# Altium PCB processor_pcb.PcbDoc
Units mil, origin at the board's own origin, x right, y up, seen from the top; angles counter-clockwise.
Board outline 4100 x 3155 mil, 2 copper layers (Top Layer, Bottom Layer); 81 components, 68 nets, 372 pads, 55 vias.
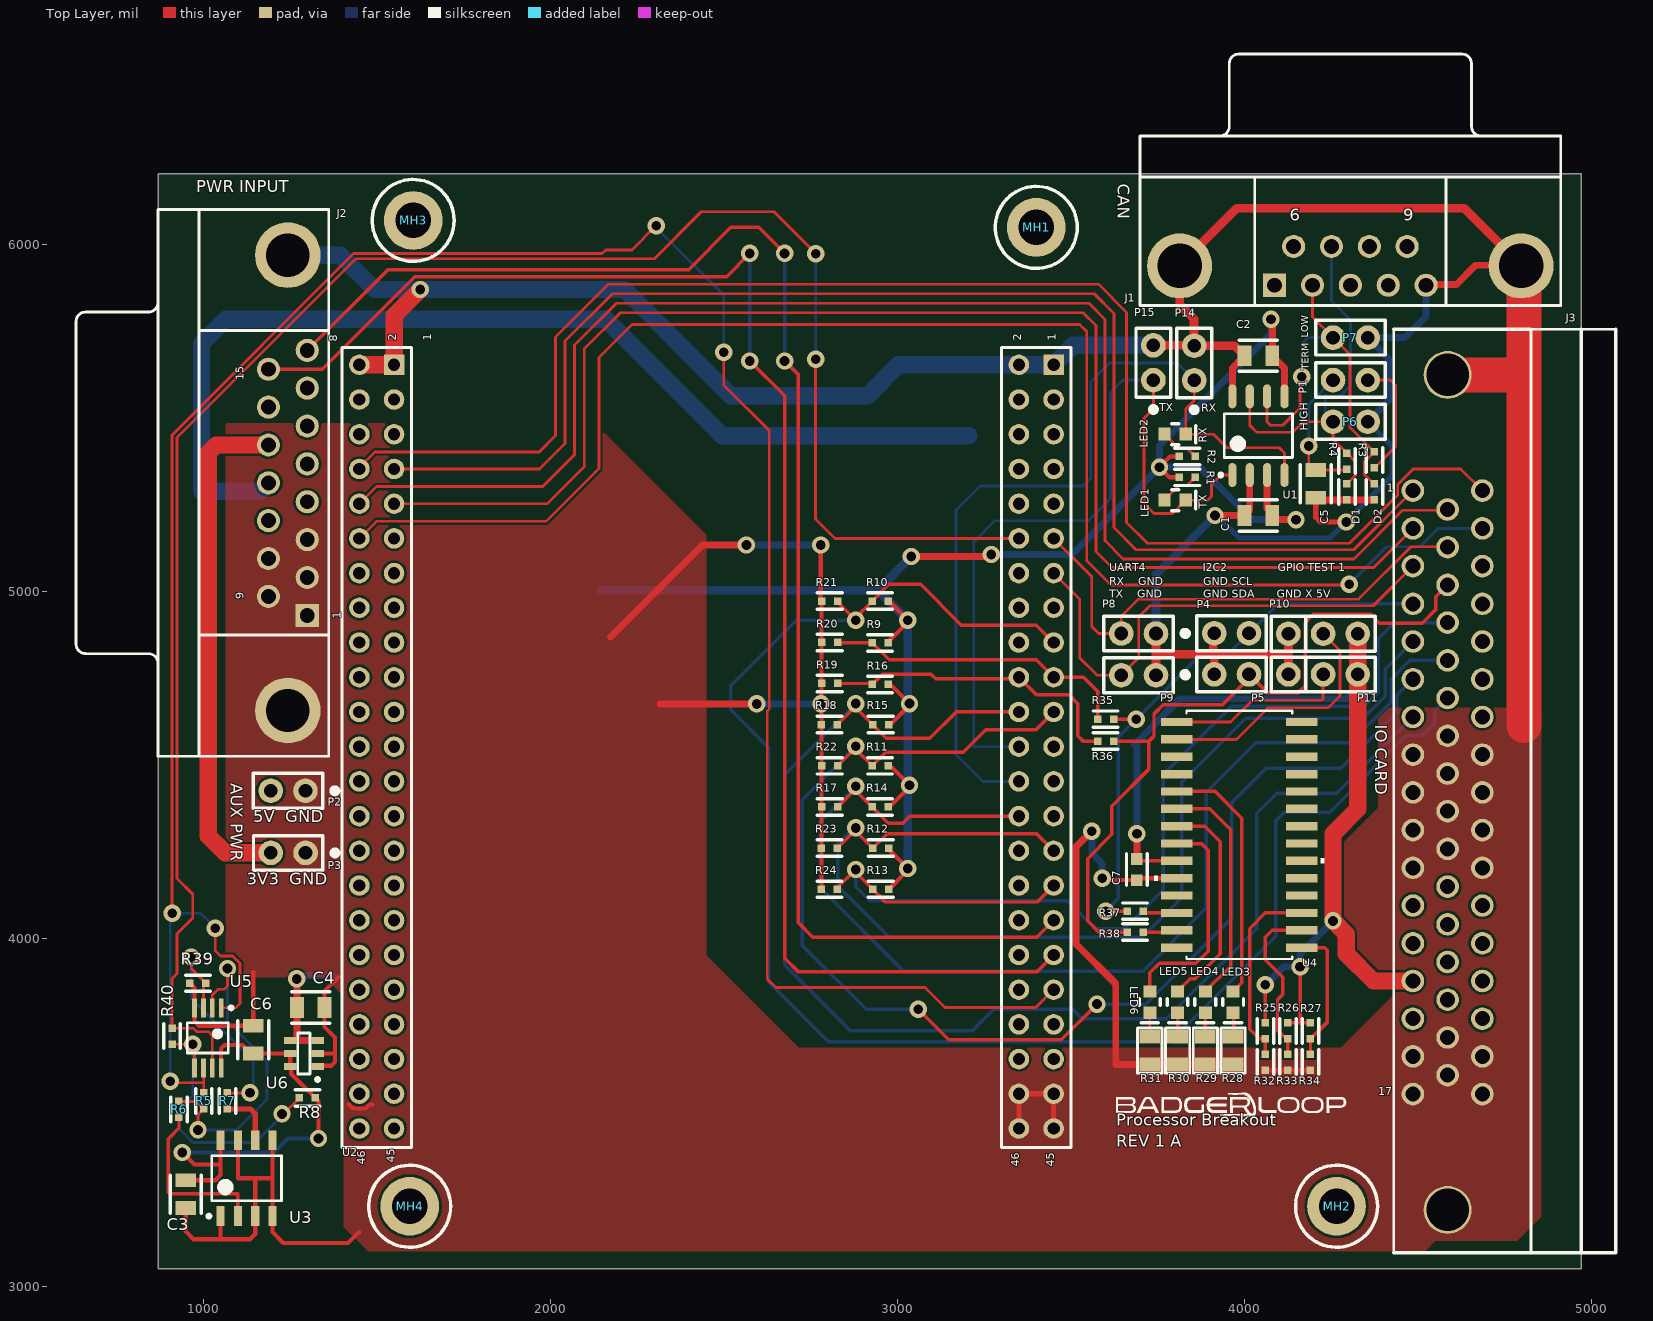
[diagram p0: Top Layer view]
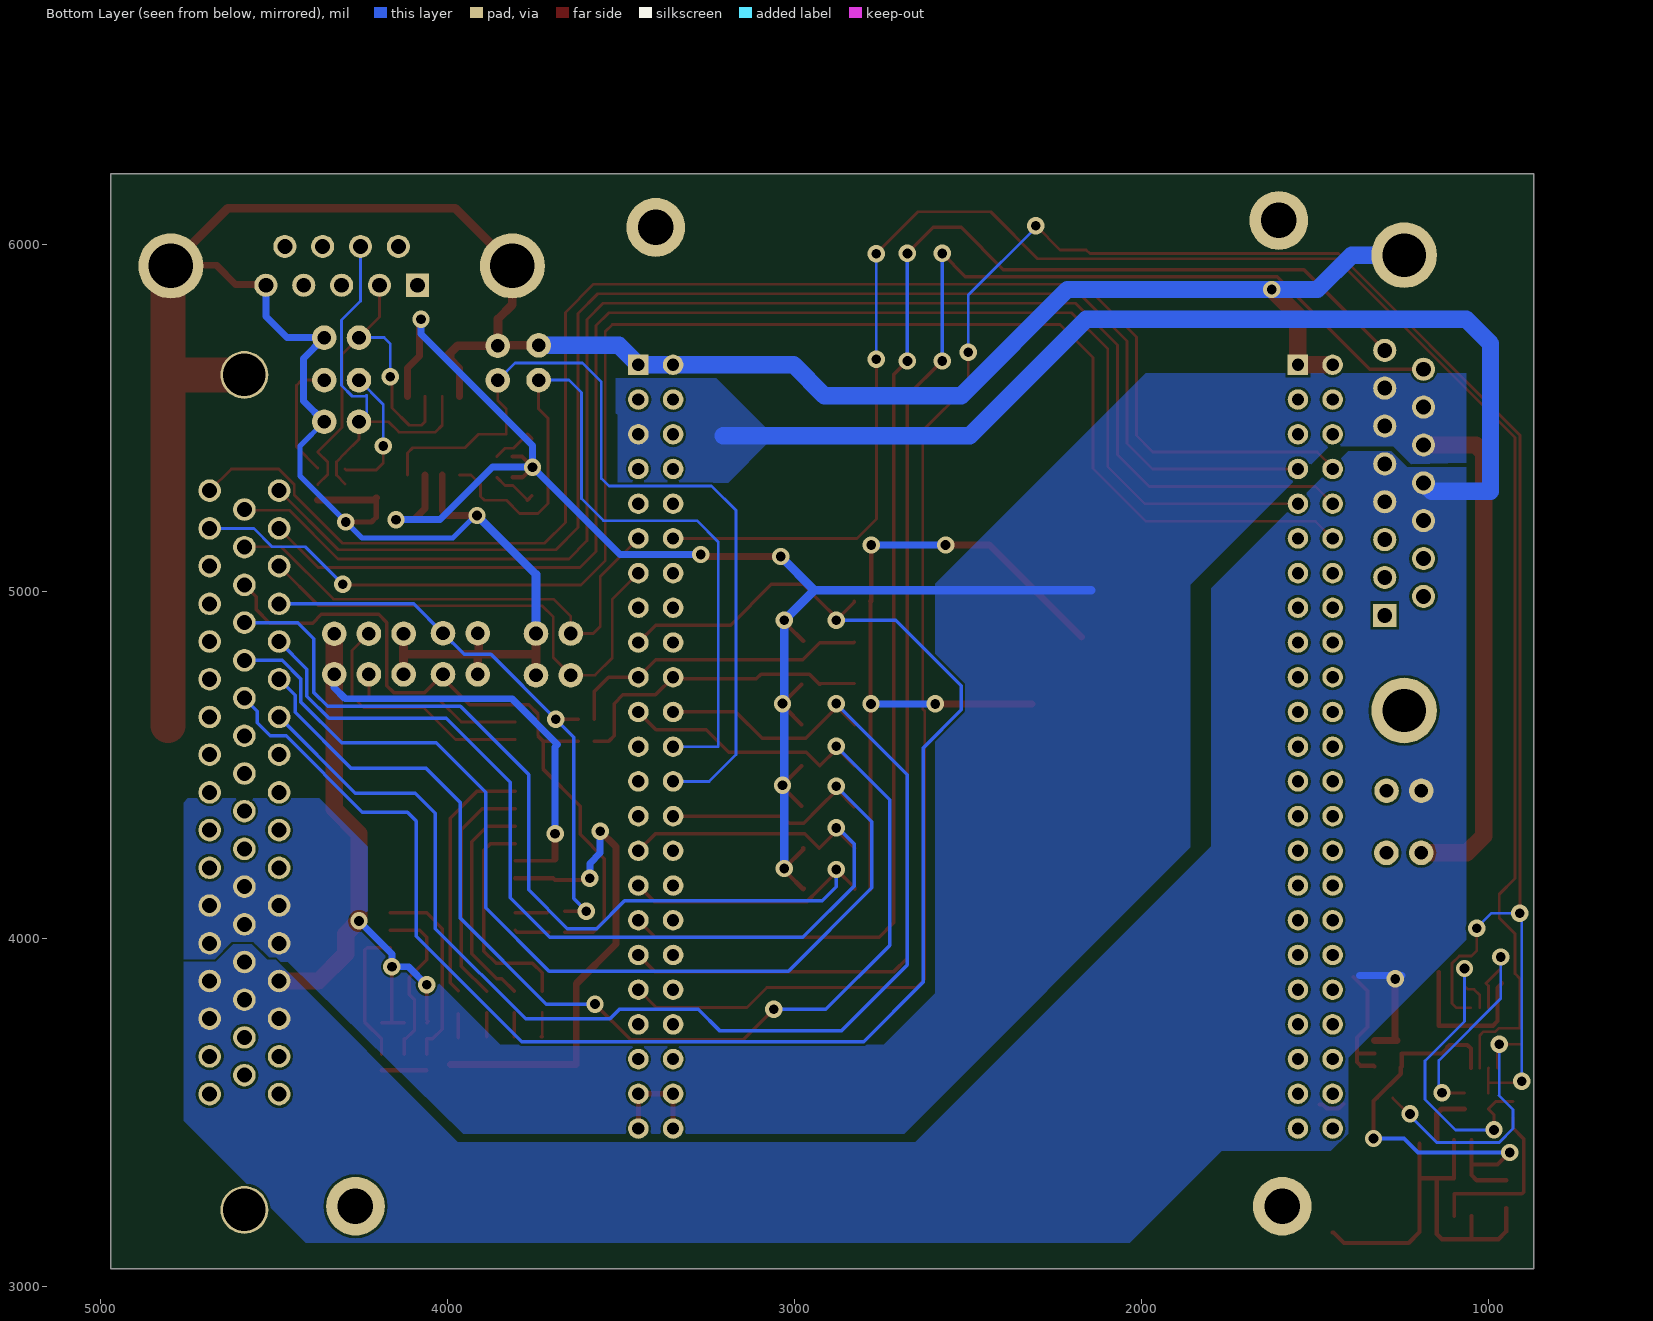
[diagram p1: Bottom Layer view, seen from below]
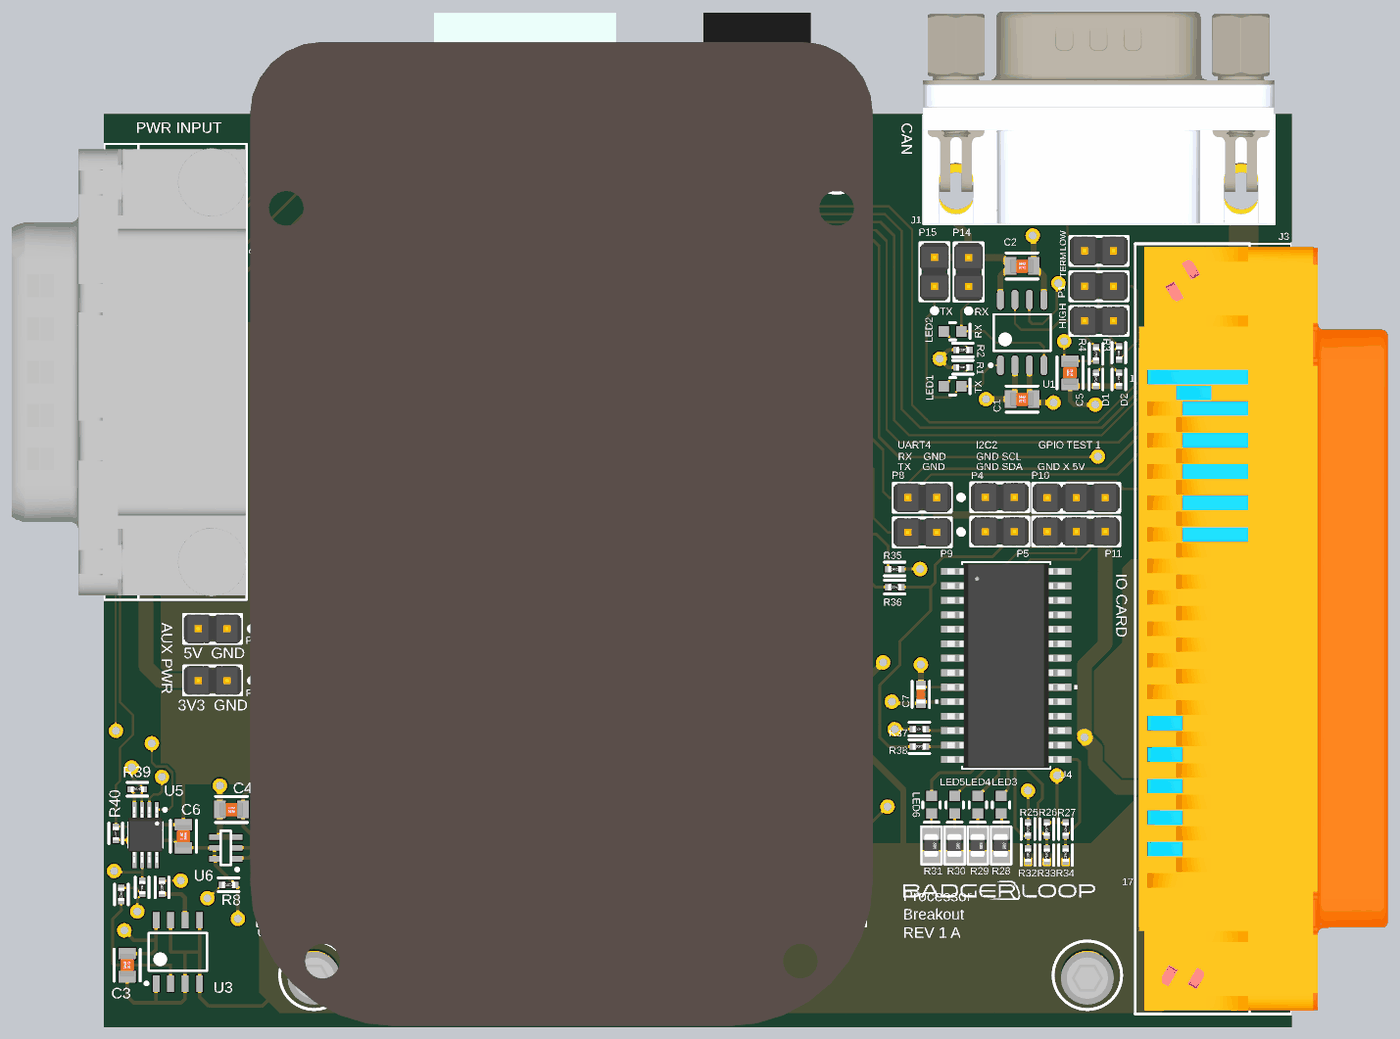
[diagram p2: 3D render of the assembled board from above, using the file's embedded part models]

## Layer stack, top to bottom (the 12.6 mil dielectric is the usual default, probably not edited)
Top Solder: solder mask 0.4, Solder Resist, Dk 3.5
Top Layer: signal copper 1.4
Dielectric 1: dielectric 12.6, FR-4, Dk 4.8
Bottom Layer: signal copper 1.4
Bottom Solder: solder mask 0.4, Solder Resist, Dk 3.5

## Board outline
870,3050 4970,3050 4970,6205 870,6205

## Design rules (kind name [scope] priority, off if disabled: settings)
AcuteAngle [All] p1: minimum=6.00000000000000E+0001 checktracksonly=FALSE
BoardOutlineClearance "Board Outline Silk Exception" [(OnLayer('Bottom Overlay') OR OnLayer('top overlay'))] p1: gap=0 ignorepadtopadclearanceinfootprint=FALSE
BoardOutlineClearance [All] p2: gap=10 ignorepadtopadclearanceinfootprint=FALSE except(0: Arc-SplitContinuation Track-SplitContinuation SMDPad-SplitContinuation THPad-SplitContinuation Via-SplitContinuation Fill-SplitContinuation Poly-SplitContinuation Region-SplitContinuation Text-SplitContinuation)
Clearance [All] p1: gap=7 ignorepadtopadclearanceinfootprint=TRUE except(0: Arc-Hole Track-Hole SMDPad-Hole THPad-Hole Via-Hole Fill-Hole Poly-Hole Region-Hole Text-Hole)
DiffPairsRouting [All] p1: maxlimit=10 minlimit=10 mostfreqgap=10 toplayer_minwidth=15 toplayer_maxwidth=15 toplayer_prefwidth=15 bottomlayer_minwidth=15 bottomlayer_maxwidth=15 bottomlayer_prefwidth=15 maxuncoupledlength=500
HoleSize [All] p1: absolutevalues=TRUE maxlimit=200 minlimit=1 maxpercent=80.000 minpercent=20.000
MinimumSolderMaskSliver [All] p1: minsoldermaskwidth=8
PlaneClearance [All] p1: clearance=50
PlaneConnect [All] p1: planeconnectstyle=Direct reliefexpansion=20 reliefentries=4 reliefconductorwidth=20 reliefairgap=10
PolygonConnect [All] p1: connectstyle=Direct reliefconductorwidth=10 reliefentries=4 polygonreliefangle="90 Angle" airgapwidth=10
RoutingVias [All] p1: holewidth=10 width=30 viastyle="Through Hole" minholewidth=10 minwidth=30 maxholewidth=10 maxwidth=30
SilkToSilkClearance [All] p1: silktosilkclearance=3
SilkToSolderMaskClearance [IsPad] p1: minsilkscreentomaskgap=2 clearancetoexposedcopper=TRUE
SolderMaskExpansion [All] p1: expansion=4
UnRoutedNet [All] p1: checkbadconnections=TRUE
Width [All] p1: maxlimit=100 minlimit=7 preferedwidth=7 minimp=50.000000 maximp=50.000000 favimp=50.000000
22 further rules are at their usual default settings.

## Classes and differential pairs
component class processor_breakout_conn: C7 J2 J3 LED3 LED4 LED5 LED6 P10 P11 R25 R26 R27 R28 R29 R30 R31 R32 R33 R34 R37 R38 U4
component class processor_beaglebone: MH1 MH2 MH3 MH4 P4 P5 P8 P9 R9 R10 R11 R12 R13 R14 R15 R16 R17 R18 R19 R20 R21 R22 R23 R24 R35 R36 U2
component class processor_main_connector: C1 C2 C3 C4 C5 C6 D1 D2 J1 LED1 LED2 P1 P2 P3 P6 P7 P14 P15 R1 R2 R3 R4 R5 R6 R7 R8 R39 R40 U1 U3 U5 U6
differential pair PRESS1: +PRESS1_P -PRESS1_N

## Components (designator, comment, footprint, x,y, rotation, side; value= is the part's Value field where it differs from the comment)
C1 "0.10µF" SMD-0805C 4040,5220 r270 top
C2 "0.10µF" SMD-0805C 4040,5680 r270 top
C3 "0.10µF" SMD-0805C 950,3265 r0 top
C4 "1µF" SMD-0805C 1310,3802.72 r90 top
C5 "4700pF" SMD-0805C 4205,5311.07 r0 top
C6 "1µF" SMD-0805C 1144.07,3710.03 r180 top
C7 "0.10µF" SMD-0603C 3690,4200 r0 top
D1 "ESD Diode" SMD-0402-RES 4295,5288.07 r180 top
D2 "ESD Diode" SMD-0402-RES 4373.88,5288.07 r180 top
J1 "D Connector 9" DSUB1.385-2H9 4305,6313.11 r0 top
J2 "D Connector 15" DSUB1.385-2H15 870,5314.06 r90 top locked
J3 "Connector 50" 050DSUB1.27-H96 4485,5291.53 r270 top
LED1 "LED ORANGE 0603" "LED 0603 ORANGE" 3799.99,5264.17 r0 top
LED2 "LED ORANGE 0603" "LED 0603 ORANGE" 3799.99,5454.17 r0 top
LED3 "RED" "LED 0603 RED" 3967,3818.37 r270 top
LED4 "RED" "LED 0603 RED" 3887,3818.37 r270 top
LED5 "GREEN" "LED 0603 GREEN" 3807,3818.37 r270 top
LED6 "GREEN" "LED 0603 GREEN" 3727,3818.37 r270 top
MH1 "4-40 Mount Hole" MH 3400,6050 r0 top
MH2 "4-40 Mount Hole" MH 4265,3230 r0 top
MH3 "4-40 Mount Hole" MH 1605,6070 r0 top
MH4 "4-40 Mount Hole" MH 1595,3230 r0 top
P1 "Header 2" "Pin Header 1x2 TH Pitch 2.54mm" 4355,5610 r180 top
P2 "Header 2" "Pin Header 1x2 TH Pitch 2.54mm" 1294.66,4426.88 r180 top
P3 "Header 2" "Pin Header 1x2 TH Pitch 2.54mm" 1295,4247.93 r180 top
P4 "Header 2" "Pin Header 1x2 TH Pitch 2.54mm" 3912.76,4880.78 r0 top
P5 "Header 2" "Pin Header 1x2 TH Pitch 2.54mm" 3912.76,4762.18 r0 top
P6 "Header 2" "Pin Header 1x2 TH Pitch 2.54mm" 4255,5490 r0 top
P7 "Header 2" "Pin Header 1x2 TH Pitch 2.54mm" 4255,5732.36 r0 top
P8 "Header 2" "Pin Header 1x2 TH Pitch 2.54mm" 3745,4880 r180 top
P9 "Header 2" "Pin Header 1x2 TH Pitch 2.54mm" 3745,4760 r180 top
P10 "Header 3" "Pin Header 1x3 TH Pitch 2.54mm" 4126.42,4879.26 r0 top
P11 "Header 3" "Pin Header 1x3 TH Pitch 2.54mm" 4126.42,4762.24 r0 top
P14 "Header 2" "Pin Header 1x2 TH Pitch 2.54mm" 3855,5609.17 r90 top
P15 "Header 2" "Pin Header 1x2 TH Pitch 2.54mm" 3737.36,5610 r90 top
R1 "120" SMD-0402-RES 3835,5330 r90 top
R2 "120" SMD-0402-RES 3835,5390 r90 top
R3 "60.4" SMD-0402-RES 4373.88,5380 r180 top
R4 "60.4" SMD-0402-RES 4295.08,5376.54 r0 top
R5 "34k" SMD-0402-RES 1001.7,3533.33 r180 top
R6 "34k" SMD-0402-RES 930,3509 r180 top
R7 "34k" SMD-0402-RES 1070,3533.33 r180 top
R8 "34k" SMD-0402-RES 1300.04,3542.36 r270 top
R9 "10k" SMD-0402-RES 2950,4853.15 r90 top
R10 "10k" SMD-0402-RES 2950,4973.15 r90 top
R11 "10k" SMD-0402-RES 2950,4498.86 r90 top
R12 "10k" SMD-0402-RES 2952,4261.72 r90 top
R13 "10k" SMD-0402-RES 2952,4143.15 r90 top
R14 "10k" SMD-0402-RES 2950,4380.29 r90 top
R15 "10k" SMD-0402-RES 2952,4617.44 r90 top
R16 "10k" SMD-0402-RES 2950,4733.15 r90 top
R17 "10k" SMD-0402-RES 2805,4380.29 r90 top
R18 "10k" SMD-0402-RES 2804,4617.44 r90 top
R19 "10k" SMD-0402-RES 2805,4736.01 r90 top
R20 "10k" SMD-0402-RES 2805,4854.58 r90 top
R21 "10k" SMD-0402-RES 2805,4973.15 r90 top
R22 "10k" SMD-0402-RES 2805,4498.86 r90 top
R23 "10k" SMD-0402-RES 2804,4261.72 r90 top
R24 "10k" SMD-0402-RES 2804,4143.15 r90 top
R25 "0.0" SMD-0402-RES 4060,3735 r180 top
R26 "0.0" SMD-0402-RES 4125,3735 r180 top
R27 "0.0" SMD-0402-RES 4190,3735 r180 top
R28 "220" SMD-0805-RES 3967,3678.37 r180 top
R29 "220" SMD-0805-RES 3887,3678.37 r180 top
R30 "220" SMD-0805-RES 3807,3678.37 r180 top
R31 "220" SMD-0805-RES 3727,3678.37 r180 top
R32 "0.0" SMD-0402-RES 4060,3645 r180 top
R33 "0.0" SMD-0402-RES 4125,3645 r180 top
R34 "0.0" SMD-0402-RES 4190,3645 r180 top
R35 "0.0" SMD-0402-RES 3600,4633.15 r270 top
R36 "0.0" SMD-0402-RES 3600,4570.25 r90 top
R37 "0.0" SMD-0402-RES 3685,4080 r90 top
R38 "0.0" SMD-0402-RES 3685,4020 r90 top
R39 "34k" SMD-0402-RES 985,3872.4 r90 top
R40 "34k" SMD-0402-RES 910.32,3720 r180 top
U1 "SN65HVD256" SOIC127P630X175-8N 4040,5450 r90 top
U2 "BEAGLEBONE Black Rev C Headers" BEAGLEBONE_TOPSIDE 1550,5653.98 r0 top
U3 "NPP-301A-100AT" SOIC127P610X280-8N 1125,3310.75 r90 top
U4 "MCP23017T-E/SO" SOIC28-W_MC-M 3985,4300 r0 top value=Value
U5 "LTC6081ISMS8#PBF" TSOP65P490X110-8N 1013.43,3715 r270 top
U6 "ADR3433" SOT95P280X145-6N 1290.32,3670 r180 top

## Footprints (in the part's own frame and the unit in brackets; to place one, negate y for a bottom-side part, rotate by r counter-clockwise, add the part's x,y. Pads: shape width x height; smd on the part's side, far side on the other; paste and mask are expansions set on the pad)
050DSUB1.27-H96 [mil] "Connector; D Subminiature; 96 Position; Right Angle; Pitch 1.27 mm"
  round 65 hole 43.31: 1(0,0) 2(108.66,0) 3(217.32,0) 4(325.98,0) 5(434.65,0) 6(543.31,0) 7(651.97,0) 8(760.63,0) 9(869.29,0) 10(977.95,0) 11(1086.61,0) 12(1195.28,0) 13(1303.94,0) 14(1412.6,0) 15(1521.26,0) 16(1629.92,0) 17(1738.58,0) 18(54.33,100) 19(162.97,100) 20(271.6,100) 21(380.24,100) 22(488.87,100) 23(597.51,100) 24(706.14,100) 25(814.78,100) 26(923.41,100) 27(1032.05,100) 28(1140.68,100) 29(1249.32,100) 30(1357.95,100) 31(1466.59,100) 32(1575.22,100) 33(1683.86,100) 34(0,200) 35(108.66,200) 36(217.32,200) 37(325.98,200) 38(434.65,200) 39(543.31,200) 40(651.97,200) 41(760.63,200) 42(869.29,200) 43(977.95,200) 44(1086.61,200) 45(1195.28,200) 46(1303.94,200) 47(1412.6,200) 48(1521.26,200) 49(1629.92,200) 50(1738.58,200)
  round 138 hole 122.05: 51(-333.46,100) 52(2072.05,100)
  silkscreen extent -465,-55 2195,585, body extent -454,-42 2184,817, height 547
BEAGLEBONE_TOPSIDE [mm] "Connector; Header; 24x2 Position"
  rect 1.5x1.5 hole 0.9: 1(48.26,0) 101(0,0)
  round 1.5 hole 0.9: 2(45.72,0) 3(48.26,-2.54) 4(45.72,-2.54) 5(48.26,-5.08) 6(45.72,-5.08) 7(48.26,-7.62) 8(45.72,-7.62) 9(48.26,-10.16) 10(45.72,-10.16) 11(48.26,-12.7) 12(45.72,-12.7) 13(48.26,-15.24) 14(45.72,-15.24) 15(48.26,-17.78) 16(45.72,-17.78) 17(48.26,-20.32) 18(45.72,-20.32) 19(48.26,-22.86) 20(45.72,-22.86) 21(48.26,-25.4) 22(45.72,-25.4) 23(48.26,-27.94) 24(45.72,-27.94) 25(48.26,-30.48) 26(45.72,-30.48) 27(48.26,-33.02) 28(45.72,-33.02) 29(48.26,-35.56) 30(45.72,-35.56) 31(48.26,-38.1) 32(45.72,-38.1) 33(48.26,-40.64) 34(45.72,-40.64) 35(48.26,-43.18) 36(45.72,-43.18) 37(48.26,-45.72) 38(45.72,-45.72) 39(48.26,-48.26) 40(45.72,-48.26) 41(48.26,-50.8) 42(45.72,-50.8) 43(48.26,-53.34) 44(45.72,-53.34) 45(48.26,-55.88) 46(45.72,-55.88) 102(-2.54,0) 103(0,-2.54) 104(-2.54,-2.54) 105(0,-5.08) 106(-2.54,-5.08) 107(0,-7.62) 108(-2.54,-7.62) 109(0,-10.16) 110(-2.54,-10.16) 111(0,-12.7) 112(-2.54,-12.7) 113(0,-15.24) 114(-2.54,-15.24) 115(0,-17.78) 116(-2.54,-17.78) 117(0,-20.32) 118(-2.54,-20.32) 119(0,-22.86) 120(-2.54,-22.86) 121(0,-25.4) 122(-2.54,-25.4) 123(0,-27.94) 124(-2.54,-27.94) 125(0,-30.48) 126(-2.54,-30.48) 127(0,-33.02) 128(-2.54,-33.02) 129(0,-35.56) 130(-2.54,-35.56) 131(0,-38.1) 132(-2.54,-38.1) 133(0,-40.64) 134(-2.54,-40.64) 135(0,-43.18) 136(-2.54,-43.18) 137(0,-45.72) 138(-2.54,-45.72) 139(0,-48.26) 140(-2.54,-48.26) 141(0,-50.8) 142(-2.54,-50.8) 143(0,-53.34) 144(-2.54,-53.34) 145(0,-55.88) 146(-2.54,-55.88)
  silkscreen extent -3.81,-57.28 49.53,1.27, body extent -4.46,-66.04 50.15,22.86, height 12.6
DSUB1.385-2H9 [mm] "Connector; D Subminiature; 9 Position; Right Angle; Pitch 1.385 mm"
  rect 1.69x1.69 hole 1.09: 1(-5.54,-10.92)
  round 1.69 hole 1.09: 2(-2.77,-10.92) 3(0,-10.92) 4(2.77,-10.92) 5(5.54,-10.92) 6(-4.155,-8.08) 7(-1.385,-8.08) 8(1.385,-8.08) 9(4.155,-8.08)
  round 4.76 hole 3.26: 10(-12.495,-9.5) 11(12.495,-9.5)
  silkscreen extent -15.4,-12.4 15.4,6, body extent -15.43,-12.37 15.37,6.22, height 12.55
DSUB1.385-2H15 [mm] "Connector; D Subminiature; 15 Position; Right Angle; Pitch 1.385 mm"
  rect 1.69x1.69 hole 1.09: 1(-9.695,-10.92)
  round 1.69 hole 1.09: 2(-6.925,-10.92) 3(-4.155,-10.92) 4(-1.385,-10.92) 5(1.385,-10.92) 6(4.155,-10.92) 7(6.925,-10.92) 8(9.695,-10.92) 9(-8.31,-8.08) 10(-5.54,-8.08) 11(-2.77,-8.08) 12(0,-8.08) 13(2.77,-8.08) 14(5.54,-8.08) 15(8.31,-8.08)
  round 4.8 hole 3.18: 16(-16.66,-9.5) 17(16.66,-9.5)
  silkscreen extent -20,-12.5 20,6, body extent -19.68,-12.47 19.64,8.13, height 13.45
"LED 0603 GREEN" [mm] "Chip Diode, 2-Leads, Body 1.60x0.80mm, IPC Medium Density"
  rect 0.9x0.95 smd: 1(-0.775,0) 2(0.775,0)
  silkscreen extent -0.25,-0.76 1.52,0.76, body extent -0.8,-0.4 0.8,0.4, height 0.8
"LED 0603 ORANGE" [mm] "Chip Diode, 2-Leads, Body 1.60x0.80mm"
  rect 0.9x0.95 smd: 1(-0.775,0) 2(0.775,0)
  silkscreen extent -0.25,-0.76 1.52,0.76, body extent -0.8,-0.4 0.8,0.4, height 0.8
"LED 0603 RED" [mm] "Chip Diode, 2-Leads, Body 1.60x0.80mm, IPC Medium Density"
  rect 0.9x0.95 smd: 1(-0.775,0) 2(0.775,0)
  silkscreen extent -0.25,-0.76 1.52,0.76, body extent -0.8,-0.4 0.8,0.4, height 0.8
MH [mm] "#10 Mount Hole"
  round 4.3 hole 2.6 unplated: 2(0,0)
  silkscreen extent -3,-3 3,3, body extent -2.32,-2.58 2.32,2.07, height 2.84
"Pin Header 1x2 TH Pitch 2.54mm" [mm] "PinHeader 1x2 TH Pitch 2.54mm"
  round 1.8 hole 1: 1(0,0) 2(2.54,0)
  silkscreen extent -1.27,-1.27 3.81,1.27, body extent -1.27,-1.27 3.81,1.27, height 9.5
"Pin Header 1x3 TH Pitch 2.54mm" [mm] "PinHeader 1x3 TH Pitch 2.54mm"
  round 1.8 hole 1: 1(0,0) 2(2.54,0) 3(5.08,0)
  silkscreen extent -1.27,-1.27 6.35,1.27, body extent -1.27,-1.27 6.35,1.27, height 9.5
SMD-0402-RES [mm]
  rect 0.55x0.55 smd: 1(0,0.584) 2(0,-0.584)
  silkscreen extent -0.6,-0.9 0.6,0.9, body extent -0.28,-0.57 0.27,0.58, height 0.41
SMD-0603C [mm]
  rect 0.85x0.85 smd: 1(0,0.775) 2(0,-0.775)
  silkscreen extent -0.76,-1.14 0.76,1.14, body extent -0.4,-0.8 0.4,0.8, height 0.9
SMD-0805-RES [mil]
  rect 60x40 smd: 1(0,40) 2(0,-40)
  silkscreen extent -35,-65 35,65, body extent -24,-39 26,39, height 31
SMD-0805C [mil]
  rect 60x40 smd: 1(0,40) 2(0,-40)
  silkscreen extent -45,-55 45,55, body extent -25,-39 25,39, height 35
SOIC28-W_MC-M [mil]
  rect 90x24 smd paste+0 mask+0: 1(-180,325) 2(-180,275) 3(-180,225) 4(-180,175) 5(-180,125) 6(-180,75) 7(-180,25) 8(-180,-25) 9(-180,-75) 10(-180,-125) 11(-180,-175) 12(-180,-225) 13(-180,-275) 14(-180,-325) 15(180,-325) 16(180,-275) 17(180,-225) 18(180,-175) 19(180,-125) 20(180,-75) 21(180,-25) 22(180,25) 23(180,75) 24(180,125) 25(180,175) 26(180,225) 27(180,275) 28(180,325)
  silkscreen extent -245,-358 245,358, body extent -203,-353 203,353, height 104
SOIC127P610X280-8N [mm] "SOIC, 8-Leads, Body 5.10x4.10mm, Pitch 1.27mm, IPC Medium Density"
  rect 1.45x0.6 smd: 1(-2.775,1.905) 2(-2.775,0.635) 3(-2.775,-0.635) 4(-2.775,-1.905) 5(2.775,-1.905) 6(2.775,-0.635) 7(2.775,0.635) 8(2.775,1.905)
  silkscreen extent -2.9,-2.55 1.65,2.88, body extent -2.05,-2.55 2.05,2.55, height 2.8
SOIC127P630X175-8N [mm] "SOIC, 8-Leads, Body 4.90x3.90mm, Pitch 1.27mm, IPC Medium Density"
  oval 1.75x0.6 smd: 1(-2.875,1.905) 2(-2.875,0.635) 3(-2.875,-0.635) 4(-2.875,-1.905) 5(2.875,-1.905) 6(2.875,-0.635) 7(2.875,0.635) 8(2.875,1.905)
  silkscreen extent -3,-2.5 1.6,2.88, body extent -2,-2.5 2,2.5, height 1.75
SOT95P280X145-6N [mm] "SOT23, 6-Leads, Body 2.90x2.80mm, Pitch 0.95mm, IPC Medium Density"
  rect 0.9x0.5 smd: 1(-1,0.95) 2(-1,0) 3(-1,-0.95) 4(1,-0.95) 5(1,0) 6(1,0.95)
  silkscreen extent -1.13,-1.5 0.45,2.02, body extent -0.85,-1.5 0.85,1.5, height 1.45
TSOP65P490X110-8N [mm] "TSOP, 8-Leads, Body 3.00x3.00mm, Pitch 0.65mm, IPC Medium Density"
  rect 1.4x0.35 smd: 1(-2.2,0.975) 2(-2.2,0.325) 3(-2.2,-0.325) 4(-2.2,-0.975) 5(2.2,-0.975) 6(2.2,-0.325) 7(2.2,0.325) 8(2.2,0.975)
  silkscreen extent -2.32,-1.5 1.1,1.83, body extent -2.45,-1.5 2.45,1.5, height 1.1

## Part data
C1 C2 C3: library part GCD21BR71H104KA01L, "CAP CER 0.1UF 50V X7R 0805", Digi-Key Part Number=490-11955-1-ND, Manufacturer="Murata Electronics North America", Operating Temperature="-55°C ~ 125°C", Package / Case="0805 (2012 Metric)", Ratings=AEC-Q200, Temperature Coefficient=X7R, Tolerance=±10%, Voltage=50V
C4: library part GCJ21BR71H105KA01L, "CAP CER 1UF 50V X7R 0805", Digi-Key Part Number=490-10667-1-ND, Manufacturer="Murata Electronics North America", Operating Temperature="-55°C ~ 125°C", Package / Case="0805 (2012 Metric)", Ratings=AEC-Q200, Temperature Coefficient=X7R, Tolerance=±10%, Voltage=50V
C5: library part GCM2165C1H472JA16D, "CAP CER 4700PF 50V NP0 0805", Digi-Key Part Number=490-4973-1-ND, Manufacturer="Murata Electronics North America", Operating Temperature="-55°C ~ 125°C", Package / Case="0805 (2012 Metric)", Ratings=AEC-Q200, Temperature Coefficient="C0G, NP0", Tolerance=±5%, Voltage=50V
C6: library part GRT21BC81E105ME13L, "CAP CER 1UF 25V X6S 0805", Digi-Key Part Number=490-12352-1-ND, Manufacturer="Murata Electronics North America", Operating Temperature="-55°C ~ 105°C", Package / Case="0805 (2012 Metric)", Ratings=AEC-Q200, Temperature Coefficient=X6S, Tolerance=±20%, Voltage=25V
C7: library part GCJ188R72A104KA01D, "CAP CER 0.1UF 100V X7R 0603", Digi-Key Part Number=490-13420-1-ND, Manufacturer="Murata Electronics North America", Operating Temperature="-55°C ~ 125°C", Package / Case="0603 (1608 Metric)", Ratings=AEC-Q200, Temperature Coefficient=X7R, Tolerance=±10%, Voltage=100V
D1 D2: "ESD Supressor", Manufacturer=EZAEG, Manufacturer P/N=Panasonic
J1: "Receptacle Assembly, 9 Position, Right Angle", PackageDocument=O
J2: "Receptacle Assembly, 15 Position, Right Angle", PackageDocument=O
J3: "Receptacle Header Assemby", PackageDocument=B
LED1 LED2: "A-0603UOC", Color=ORANGE, Manufacturer="Lighthouse LEDs", Package / Case=0603
LED3 LED4: library part "LED RED 0603", "Red 631nm LED Indication - Discrete 2V 0603 (1608 Metric)", Manufacturer="Lite-On Inc.", Manufacturer P/N=LTST-C190KRKT, Package / Case=0603
LED5 LED6: library part "LED GREEN 0603", Manufacturer="Lite-On Inc.", Manufacturer P/N=LTST-C190KGKT, Package / Case=0603
P1 P2 P3 P4 P5 P6 P7 P8 P9 P14 P15: "Header, 2-Pin"
P10 P11: "Header, 3-Pin"
R1 R2: library part ERJ-2GEJ121X, "RES SMD 120 OHM 5% 1/10W 0402", Digi-Key Part Number=P120JCT-ND, Manufacturer="Panasonic Electronic Components", Operating Temperature="-55°C ~ 155°C", Package / Case="0402 (1005 Metric)", Power (Watts)="0.1W, 1/10W", Supplier Device Package=0402, Temperature Coefficient=±200ppm/°C, Tolerance=±5%
R3 R4: library part ERJ-2RKF60R4X, "RES SMD 60.4 OHM 1% 1/10W 0402", Digi-Key Part Number=P60.4LCT-ND, Manufacturer="Panasonic Electronic Components", Operating Temperature="-55°C ~ 155°C", Package / Case="0402 (1005 Metric)", Power (Watts)="0.1W, 1/10W", Supplier Device Package=0402, Temperature Coefficient=±100ppm/°C, Tolerance=±1%
R5 R6 R7 R8 R39 R40: library part ERJ-2RKF3402X, "RES SMD 34K OHM 1% 1/10W 0402", Digi-Key Part Number=P34.0KLCT-ND, Manufacturer="Panasonic Electronic Components", Operating Temperature="-55°C ~ 155°C", Package / Case="0402 (1005 Metric)", Power (Watts)="0.1W, 1/10W", Supplier Device Package=0402, Temperature Coefficient=±100ppm/°C, Tolerance=±1%
R9 R10 R11 R12 R13 R14 R15 R16 R17 R18 R19 R20 R21 R22 R23 R24: library part ERJ-2GEJ103X, "RES SMD 10K OHM 5% 1/10W 0402", Digi-Key Part Number=P10KJCT-ND, Manufacturer="Panasonic Electronic Components", Operating Temperature="-55°C ~ 155°C", Package / Case="0402 (1005 Metric)", Power (Watts)="0.1W, 1/10W", Supplier Device Package=0402, Temperature Coefficient=±200ppm/°C, Tolerance=±5%
R25 R26 R27 R32 R33 R34 R35 R36 R37 R38: library part ERJ-2GE0R00X, "RES SMD 0.0OHM JUMPER 1/10W 0402", Digi-Key Part Number=P0.0JCT-ND, Manufacturer="Panasonic Electronic Components", Operating Temperature="-55°C ~ 155°C", Package / Case="0402 (1005 Metric)", Power (Watts)="0.1W, 1/10W", Supplier Device Package=0402, Temperature Coefficient=-, Tolerance=Jumper
R28 R29 R30 R31: library part ERJ-6ENF2200V, "RES SMD 220 OHM 1% 1/8W 0805", Digi-Key Part Number=P220CCT-ND, Manufacturer="Panasonic Electronic Components", Operating Temperature="-55°C ~ 155°C", Package / Case="0805 (2012 Metric)", Power (Watts)="0.125W, 1/8W", Supplier Device Package=0805, Temperature Coefficient=±100ppm/°C, Tolerance=±1%
U1: "IC TXRX CAN 5V HS 8SOIC", Manufacturer=TI, Manufacturer P/N=SN65HVD256DR
U2: library part Beaglebone, "Beaglebone Black Rev C Header"
U3: "SENSOR PRES 15PSIA SO8 SMD", Manufacturer="Amphenol Advanced Sensors"
U4: "Imported"
U5: "IC OPAMP GP 3.5MHZ RRO 8MSOP", Manufacturer="Linear Technology", Manufacturer P/N=LTC6081IMS8#PBF
U6: "IC VREF SERIES 3.3V SOT23-6", Manufacturer="Analog Devices", Manufacturer P/N=ADR3433ARJZ-R7

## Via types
v1: diameter 50, hole 28, Top Layer to Bottom Layer, 55 vias

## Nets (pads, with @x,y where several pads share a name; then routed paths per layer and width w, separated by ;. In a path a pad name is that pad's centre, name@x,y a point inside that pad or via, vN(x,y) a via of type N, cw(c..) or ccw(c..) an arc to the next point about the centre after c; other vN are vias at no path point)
3V3_PRESS_IN: C3.1 C6.1 R8.1 U3.8 U5.8 U6.5 U6.6 | length 1290.2
  Top Layer w12: v1(940,3385) 975,3350 1050,3350 ; C3.1 1035,3305 1050,3320 1050,3350 ; U3.8 1050,3350 ; U5.8 1051.81,3684.57 1062.24,3695 1113.04,3695 1120.07,3687.97 1120.07,3684.03 1134.07,3670.03 C6.1 U6.5 ; U6.5 U6.6 1253.61,3629.93 1253.61,3611.79 R8.1 1332.07,3533.33 v1(1332.07,3425)
  Bottom Layer w12: v1(940,3385) 1203.91,3385 1243.91,3425 v1(1332.07,3425)
AIN0: U2.39
CAN1_H: D1.2 J1.7 P6.1 R4.1 U1.7 | length 1157.1
  Top Layer w8: U1.7 4015,5480 4035,5460 4140,5460 4170,5490 P6.1 4255,5439.61 R4.1 4320,5374.61 4320,5336.07 D1.2
  Bottom Layer w8: J1.7@4250.47,5996.81 4250.47,5837.39 4305,5782.87 4305,5594.33 4274.23,5563.57 4235.77,5563.57 4232.77,5566.56 4232.77,5512.23 P6.1
CAN1_L: D2.2 J1.2 P7.1 R3.2 U1.6 | length 1150.4
  Top Layer w8: U1.6 4065,5490 4075,5480 4110,5480 4160,5530 4160,5615 v1(4165,5620) ; J1.2@4195.94,5885 4195.94,5791.42 P7.1 4303.6,5683.76 4303.6,5473.28 R3.2 4345,5374.12 4345,5338.43 D2.2@4373.88,5309.55
  Bottom Layer w8: v1(4165,5620) 4165,5715 4182.36,5732.36 P7.1
CAN1_RX: LED2.2 P14.1 U1.4 U2.26 | length 2497.7
  Top Layer w8: P14.1 3855,5551.36 3830.5,5526.86 LED2.2 3910.83,5454.17 3950,5415 4100,5415 4115,5400 U1.4
  Bottom Layer w8: U2.26 3246.02,4453.98 3168.98,4531.02 3168.98,5235 3238.98,5305 3535,5305 3556.65,5326.65 3556.65,5605 3610.83,5659.17 3805,5659.17 P14.1
CAN1_TX: LED1.2 P15.1 U1.1 U2.24 | length 2309.4
  Top Layer w8: P15.1 3737.36,5527.36 3710,5500 3710,5255 3739.21,5225.79 3792.12,5225.79 LED1.2 3894.17,5264.17 3905,5275 3905,5310 3931.81,5336.81 U1.1
  Bottom Layer w8: U2.24 3220,4553.98 3220,5143.98 3281.02,5205 3550.68,5205 3614.17,5268.49 3614.17,5574.17 3650,5610 P15.1
CURR_SENSE: J2.15 U2.35 | length 4408.4
  Top Layer w10: J2.15 1342.84,5641.22 1609.67,5908.05 1968.05,5908.05 2508.05,5908.05 v1(2575,5975) ; v1(2575,5665) 2675,5565 2675,3945 2715,3905 3401.02,3905 U2.35
  Bottom Layer w10: v1(2575,5665) v1(2575,5975)
GND: C1.2 C2.2 C3.2 C4.2 C5.2 C6.2 C7.2 D1.1 D2.1 J1.5 J1.10 J1.11 J2.1 J2.2 J2.3 J2.9 J2.10 J2.16 J2.17 J3.8 J3.9 J3.10 J3.11 J3.16 J3.17 J3.24 J3.25 J3.26 J3.27 J3.32 J3.33 J3.41 J3.42 J3.43 J3.44 J3.49 J3.50 J3.51 J3.52 P2.1 P3.1 P4.1 P5.1 P6.2 P7.2 P8.1 P9.1 P10.1 P11.1 P14.2 P15.2 R17.1 R18.1 R19.1 R20.1 R21.1 R22.1 R23.1 R24.1 R28.1 R29.1 R30.1 R31.1 R32.1 R33.1 R34.1 R39.1 U1.2 U1.8 U2.1 U2.2 U2.43 U2.44 U2.45 U2.46 U2.101 U2.102 U3.1 U3.3 U3.4 U3.5 U3.7 U4.10 U5.4 U6.1 U6.2 | length 15976.4
  Top Layer w12: C3.2 950,3157 972,3135 1050,3135 ; R39.1 975.04,3859.36 U5.4 975.04,3763.27 988.28,3750.03 C6.2 1144.07,3904.92 1144,3905 ; U3.1 1050,3135 ; U3.7 1100,3310.75 1150,3310.75 ; U3.5@1200,3410 1200,3310.75 ; U6.1 1332.09,3635 1369.87,3635 1380,3645.13 1380,3670 ; U6.2 1380,3670 ; 1390,3890.82 1390,3890.33 1350,3850.33 C4.2 1350,3746.17 1380,3716.17 1380,3670 ; 1419.22,3524.62 1432.38,3511.45 1467.62,3511.45 1479.72,3523.55 1487.59,3523.55 ; 1450,3154.62 1447.71,3154.62 1417.66,3124.56 1230.83,3124.56 1200,3155.39 U3.4 1200,3310.75 ; R21.1@2779,4973.15 2781,4971.15 2781,4677.18 R18.1 R23.1 R24.1 ; v1(2779,5135) 2779,5062.26 ; 2780,5061.26 2779,5062.26 ; R21.1 2779,4976.15 2779,5062.26 ; v1(3590,4175) 3590,4173.2 3586.29,4169.49 C7.2 3695.51,4175 U4.10 ; R32.1 R33.1 R34.1 ; 1050,3135 1135,3135 1150,3150 U3.3 1150,3310.75 ; 1150,3310.75 1200,3310.75
  Top Layer w15: U2.46 U2.44 U2.43 U2.45 ; C5.2 4205,5215 4218.93,5201.07 v1(4292.61,5201.07)
  Top Layer w20: 2174.01,4870.26 2438.76,5135 v1(2565,5135) ; 2315.86,4677.18 v1(2595,4677.18) ; v1(3560,4310.72) 3515,4265.72 3515,3985 3629.07,3870.93 3629.07,3638.37 R31.1 R30.1 R29.1 R28.1 R28.1@3992,3638.37 ; v1(3915,5220) C1.2 4015,5235 U1.2 ; U1.8 3965,5645 3990,5670 C2.2@3990,5680 ; C5.2 4211,5265.07 D1.1 D2.1 ; J1.5@4523.11,5885 4610,5885 4665.91,5940.91 J1.11@4796.93,5940.91
  Top Layer w25: P15.2 P14.2@3854.17,5710 ; P9.1 3745,4820 ; P8.1 3745,4820 ; P5.1 3912.76,4817.24 3910,4820 ; P4.1 3910,4878.02 3910,4820 ; C2.2 3970.83,5709.17 P14.2 P14.2@3854.17,5710 ; P11.1 4126.42,4820 ; P10.1 4126.42,4820 ; J1.11@4796.93,5940.91 4632.83,6105 3977.17,6105 3813.07,5940.91 J1.10 3813.07,5826.93 3854.17,5785.83 P14.2@3854.17,5710 ; 3745,4820 3910,4820 ; 3910,4820 4126.42,4820
  Top Layer w50: U2.102 U2.101 1550,5796.05 v1(1625,5871.05)
  Top Layer w100: J3.51 4795,5625 4805,5615 ; J1.11@4796.93,5940.91 4805,5932.83 4805,5615 ; 4805,4615 4805,5615
  Bottom Layer w15: v1(3915,5220) 3920,5220 3985,5155 4246.54,5155 v1(4292.61,5201.07) 4425,5333.46 4425,5420 P6.2
  Bottom Layer w20: v1(2565,5135) v1(2779,5135) ; v1(2595,4677.18) v1(2780,4677.18) ; v1(3560,4310.72) 3560,4247.15 3590,4217.15 v1(3590,4175) ; P6.2 4415,5550 4415,5672.36 P7.2 4462.42,5732.36 4523.11,5793.06 J1.5 J1.5@4523.11,5885
  Bottom Layer w25: P8.1 3745,5050 v1(3915,5220)
  Bottom Layer w50: J2.17 1395.04,5969.96 1493.95,5871.05 v1(1625,5871.05) 2213.95,5871.05 2520,5565 2913.97,5565 3002.95,5653.98 U2.2 U2.1 3506.02,5710 P15.2
GPIO_44: J3.35 U2.112 | length 4442.5
  Top Layer w8: U2.112 1499.17,5203.15 1988.15,5203.15 2140,5355 2140,5675 2235,5770 3525,5770 3545.68,5749.32 3545.68,5089.32 3615.2,5019.8 4299.43,5019.8 v1(4301.52,5021.89)
  Bottom Layer w8: v1(4301.52,5021.89) 4409.63,5130 4505,5130 4557.87,5182.87 J3.35
GPIO_49: U2.23
GPIO_66: J3.1 U2.107 | length 4054.2
  Top Layer w8: U2.107 1968.98,5353.98 2042.57,5427.57 2042.57,5722.29 2179.12,5858.84 3566.94,5858.84 3623.92,5801.86 3623.92,5184.99 3687.71,5121.2 4314.67,5121.2 J3.1
GPIO_67: J3.34 U2.108 | length 4414.5
  Top Layer w8: U2.108@1450.66,5359.34 1494.47,5403.15 1968.15,5403.15 2015.1,5450.1 2015.1,5733.67 2167.74,5886.32 3522.16,5886.32 3578.83,5886.32 3660,5805.15 3660,5200 3720,5140 4302.13,5140 4441.5,5279.37 4441.5,5309.55 4485.92,5353.98 4622.56,5353.98 J3.34
GPIO_68: J3.18 U2.110 | length 4295.7
  Top Layer w8: U2.110 1499.17,5303.15 1978.15,5303.15 2070.05,5395.05 2070.05,5710.91 2190.5,5831.36 3551.42,5831.37 3597.84,5784.95 3597.84,5147.4 3650.24,5095 4315,5095 4455,5235 J3.18@4585,5235
GPIO_69: J3.2 U2.109 | length 4093.8
  Top Layer w8: U2.109 1991.42,5253.98 2097.52,5360.08 2097.52,5699.53 2201.88,5803.89 3535.09,5803.89 3571.76,5767.22 3571.76,5116.1 3617.86,5070 4372.13,5070 J3.2
GPIO_115: U2.27
GPIO_117: U2.25
GPIO_A_0: U4.21
GPIO_A_1: U4.22
GPIO_A_2: U4.23
GPIO_A_3: U4.24
GPIO_A_4: U4.25
GPIO_A_5: U4.26
GPIO_A_6: U4.27
GPIO_A_7: U4.28
I2C2_SCL: J3.4 P4.2 R35.1 R37.1 | length 1646.6
  Top Layer w10: v1(3600,4080) R37.1 ; R35.1 v1(3687.71,4633.15)
  Bottom Layer w10: v1(3600,4080) 3636.67,4116.67 3636.67,4581.67 3677.71,4622.71 v1@3687.71,4622.71 ; v1(3687.71,4633.15) 3874.56,4820 3951.98,4820 P4.2 4097.53,4965.55 J3.4
I2C2_SCL_BB: R9.1 R20.2 R35.2 U2.19 | length 887.5
  Top Layer w10: R20.2 2829.43,4853.15 R9.1 2975.95,4804.2 3399.78,4804.2 U2.19 3536.02,4753.98 3577,4713 R35.2
I2C2_SDA: J3.20 P5.2 R36.2 R38.1 | length 2102.3
  Top Layer w10: R36.2 3724.71,4570.25 ; R38.1 3580,4020 3548,4052 3548,4231.58 3617.86,4301.45 3617.86,4382.86 3724.71,4489.71 3724.71,4570.25 ; J3.20 4550.93,4985.86 4550.93,4949.07 4511.85,4910 4388.15,4910 4363.15,4935 4198.3,4935 4175,4911.7 4175,4730 4155,4710 4065,4710 P5.2 P5.2 4012.76,4751.38 3936.38,4675 3766.16,4675 3739.21,4648.05 3739.21,4584.75 3724.71,4570.25
I2C2_SDA_BB: R16.1 R19.2 R36.1 U2.20 | length 900.6
  Top Layer w10: R19.2 2924.14,4736.01 R16.1 2957,4763.15 3096.61,4763.15 3110,4749.76 3345.79,4749.76 U2.20 3400.83,4703.15 3495,4703.15 3520,4678.15 3520,4585 3534.75,4570.25 R36.1
I2C_RESET: U4.18
INTA_1: U4.20
INTB_1: U4.19
LED_GPB4: LED3.1 U4.5 | length 725.5
  Top Layer w10: U4.5 3915,4425 3992,4348 3992,3873.89 LED3.1@3969,3850.89
LED_GPB5: LED4.1 U4.6 | length 676.2
  Top Layer w10: U4.6 3900,4375 3960,4315 3960,3921.89 LED4.1
LED_GPB6: LED5.1 U4.7 | length 634.3
  Top Layer w10: U4.7 3885,4325 3930,4280 3930,3957.24 3857.76,3885 3843.11,3885 LED5.1
LED_GPB7: LED6.1 U4.8 | length 636.2
  Top Layer w10: LED6.1 3727,3902.38 3727.38,3902.38 3755,3930 3860,3930 3895,3965 3895,4255.83 3875.83,4275 U4.8
NetC5_1: C5.1 P1.2 R4.2 | length 387.3
  Top Layer w8: v1(4185,5420) 4185,5371.07 C5.1 4292.61,5351.07 R4.2
  Bottom Layer w8: v1(4185,5420) 4185,5540 P1.2
NetLED1_1: LED1.1 R1.2 | length 133.4
  Top Layer w8: LED1.1 3811.69,5306.38 3834.38,5306.38 R1.2
  Top Layer w10: LED1.1@3756.99,5276.66 LED1.1
NetLED2_1: LED2.1 R2.2 | length 132.8
  Top Layer w8: LED2.1 3810.03,5413.62 3834.38,5413.62 R2.2
  Top Layer w10: LED2.1@3756.99,5441.68 LED2.1
NetLED3_2: LED3.2 R28.2 | length 69.5
  Top Layer w10: R28.2@3969,3715.37 LED3.2@3969,3784.86
NetLED4_2: LED4.2 R29.2 | length 69.5
  Top Layer w10: R29.2 LED4.2
NetLED5_2: LED5.2 R30.2 | length 69.5
  Top Layer w10: R30.2 LED5.2
NetLED6_2: LED6.2 R31.2 | length 72.5
  Top Layer w8: R31.2 LED6.2
  Top Layer w10: R31.2 R31.2@3730,3718.37
NetP1_1: P1.1 R3.1 | length 349.5
  Top Layer w8: P1.1 4420,5610 4435,5595 4435,5418.12 R3.1
NetR5_1: R5.1 R6.2 U5.2 | length 949.4
  Top Layer w8: R6.2 980.03,3532 R5.1 985,3493.63 v1(985,3450) ; U5.2 1026.22,3838.82 1042.4,3855 1060,3855 1070,3865 v1(1070,3915)
  Bottom Layer w8: v1(985,3450) 1096,3450 1183.92,3537.92 1183.92,3648.89 1070,3762.81 v1(1070,3915)
NetR7_2: R7.2 R39.2 U5.3 | length 700
  Top Layer w8: v1(965.74,3947.93) 965.74,3914.66 R39.2 1000.63,3865.03 U5.3 ; R7.2 1134.2,3556.33 v1(1134.97,3557.1)
  Bottom Layer w8: v1(965.74,3947.93) 965.74,3828.33 1144.07,3650 v1@1144.07,3553.98
NetR8_2: R8.2 R40.1 U5.5 | length 806.2
  Top Layer w8: R40.1 958,3697 975.04,3679.96 U5.5 ; v1(1226.91,3496.01) 1230.7,3496.01 R8.2
  Bottom Layer w8: v1(970,3697) 970,3549.94 970.47,3549.47 930,3509 930,3454.09 970.09,3414 1150.02,3414 1224.92,3488.9 v1@1224.92,3500
NetR25_1: R25.1 R32.2 U4.17 | length 559.2
  Top Layer w10: R32.2 R25.1 4043,3712 4015,3740 4015,4030 4060,4075 U4.17
NetR26_1: R26.1 R33.2 U4.16 | length 492.6
  Top Layer w10: R33.2 R26.1 4120,3712 4095,3737 4095,3825 4110,3840 4110,3890 4060,3940 4060,4005 4080,4025 U4.16
NetR27_1: R27.1 R34.2 U4.15 | length 396.4
  Top Layer w10: U4.15 4230.83,3975 4238.86,3966.97 4238.86,3760.86 R27.1 R34.2
NetR37_2: R37.2 U4.12 | length 99.1
  Top Layer w10: R37.2 3713,4075 U4.12
NetR38_2: R38.2 U4.13 | length 99.1
  Top Layer w10: R38.2 3800,4020 U4.13
POS3V3: C1.1 C2.1 J2.6 J2.7 J2.13 J2.14 J3.12 J3.13 J3.28 J3.29 J3.45 J3.46 P3.2 R1.1 R2.1 R9.2 R10.2 R11.2 R12.2 R13.2 R14.2 R15.2 R16.2 U1.3 U1.5 | length 6254.1
  Top Layer w12: R13.2@2973,4145.15 R13.2 v1@3020,4188.15 ; R12.2 2975,4258.15 v1(3030,4203.15) ; R9.2@2975,4858.15 v1@3020,4903.15 ; R10.2@2975,4973.15 v1(3030,4918.15) ; R14.2@2980,4383.15 v1@3025,4428.15 ; R11.2@2980,4498.15 v1(3035,4443.15) ; R15.2@2980,4618.15 v1@3025,4663.15 ; R16.2@2980,4733.15 v1(3035,4678.15) ; R1.1 3784.34,5330 v1(3755,5359.34) 3785.66,5390 R2.1
  Top Layer w20: v1(3040,5101.85) 3264.4,5101.85 v1(3270,5107.45) ; U1.3 4065,5240 C1.1@4085,5220 ; v1(4076.42,5785) 4080,5781.42 C2.1 4115,5645 U1.5 ; C1.1 C1.1@4085,5220 ; v1@4148.27,5220 v1(4148.27,5208.07) 4096.93,5208.07 C1.1@4085,5220
  Top Layer w50: J2.13 1038.11,5423.11 1015,5400 1015,4296.72 1063.78,4247.93 P3.2@1194.66,4247.93
  Bottom Layer w20: v1(3270,5107.45) 3503.11,5107.45 v1(3755,5359.34) ; v1(4076.42,5785) 4076.42,5742.8 3755,5421.38 v1(3755,5359.34) ; v1(4148.27,5208.07) 4021.3,5208.07 3870.03,5359.34 v1(3755,5359.34)
  Bottom Layer w25: 2145,5004.95 2464.07,5004.95 2464.12,5005 2943.15,5005 ; v1(3030,4203.15) v1(3030,4918.15) 2943.15,5005 ; v1(3040,5101.85) 2943.15,5005
POS5V: C4.1 C7.1 J2.4 J2.5 J2.11 J2.12 J3.14 J3.15 J3.30 J3.31 J3.47 J3.48 P2.2 P10.3 P11.3 R25.2 R26.2 R27.2 U2.5 U4.9 U6.3 U6.4 | length 6400.1
  Top Layer w10: C7.1 3695.51,4225 U4.9 ; R25.2 4055,3763 4060,3768 v1(4060,3867.95) ; R26.2 4157.5,3758 ; v1(4160,3920) 4160,3760.66 4160.08,3760.58 4157.5,3758 ; R27.2 4157.5,3758
  Top Layer w20: v1(1270,3885) 1270,3802.83 C4.1@1270.05,3802.78 ; C4.1@1270.63,3803.35 C4.1@1270.05,3802.78 ; U6.3 1265,3707.4 1270,3712.4 C4.1 C4.1@1270.05,3802.78 ; C7.1 v1(3690,4303.12)
  Top Layer w50: P10.3 P11.3 4326.42,4374.54 4255,4303.12 v1(4255,4052) 4292.64,4014.36 4292.64,3957.77 4371.47,3878.94 J3.14
  Bottom Layer w20: v1@1249.66,3894.22 1372.07,3894.22 ; v1(3690,4303.12) 3690,4553.22 3682.76,4560.47 3814.29,4692 4294.4,4692 4326.42,4724.02 P11.3 ; v1(4060,3867.95) 4112.05,3920 v1(4160,3920) 4160,3957 v1(4255,4052)
  Bottom Layer w50: J2.12 1164.06,5290 995,5290 995,5715 1065,5785 2160,5785 2495,5450 3205,5450
PRESS1_AMP: R5.2 U2.37 U5.1 U5.6 | length 7325.5
  Top Layer w8: v1(905,3590) 909.12,3585.88 1000.82,3585.88 1001.7,3585 ; v1@910,4080.03 910,5451.21 1433.14,5974.35 2149.35,5974.35 2160,5985 2235,5985 v1(2305,6055) ; U5.6 1001.7,3627.31 1001.7,3585 ; R5.2 1001.7,3585 ; v1(1035,4031.2) 1035,3965.91 1049.91,3951 1084.91,3951 1106,3929.91 1106,3814.39 1093.22,3801.61 U5.1 ; v1(2500,5690) 2500,5595 2631,5464 2631,4662.27 2625,4656.27 2625,3885 2650,3860 3080,3860 3137.37,3802.63 3398.65,3802.63 U2.37
  Bottom Layer w8: v1(905,3590) 905,4068.19 v1(911.16,4074.35) 991.85,4074.35 v1(1035,4031.2) ; v1@2304.43,6050 2500,5854.43 v1(2500,5690)
PRESS1_COMP: R40.2 U2.12 U5.7 | length 5486
  Top Layer w8: U5.7 1026.22,3721.89 1015.08,3733.03 981.24,3733.03 971.27,3743 R40.2 910.32,3885.32 925,3900 925,4015 970,4060 970,4128.99 925,4173.99 925,5445 1439.35,5959.35 2299.35,5959.35 2435,6095 2644.09,6095 v1(2765,5974.09) ; v1@2755,5665 2764,5656 2764,5210 2820.02,5153.98 U2.12
  Bottom Layer w8: v1(2764.43,5670) 2764.43,5964.43 v1@2765,5965
PRESS1_N: R6.1 U3.2 | length 494.3
  Top Layer w8: 930,3455 R6.1
  Top Layer w10: 930,3455 900,3425 900,3270 904.53,3265.47 1100,3265.47 U3.2
PRESS1_P: R7.1 U3.6 | length 162.3
  Top Layer w15: R7.1 1136.24,3510.33 1150,3496.57 U3.6
SPI0_CSO: J3.23 R10.1 R21.2 U2.17 | length 4752.7
  Top Layer w10: R21.2 2828,4970.15 v1(2880,4918.15) 2880,4926.15 R10.1 2975.32,5021.47 3066.68,5021.47 3184.02,4904.13 3399.84,4904.13 U2.17
  Bottom Layer w10: v1(2880,4918.15) 2708.15,4918.15 2520,4730 2520,4660 2630,4550 2630,3875 2801.1,3703.9 3786.31,3703.9 4089.7,4007.28 4089.7,4339.87 4115.13,4365.3 4245.3,4365.3 4465,4585 4510,4585 4547.5,4622.5 4547.5,4656.53 J3.23
SPI0_DO: J3.6 R11.1 R22.2 U2.21 | length 3898.9
  Top Layer w10: R22.2 2877.5,4548.36 v1@2880,4550.86 ; v1(2880,4555) v1@2880,4550.86 ; v1(3060,3797.45) 3147.45,3710 3472.55,3710 v1(3575,3812.45) ; U2.21 3399.17,4603.15 3255,4603.15 3190,4538.15 2966.29,4538.15 R11.1 2880,4545.86 v1@2880,4550.86
  Bottom Layer w10: v1(2880,4555) 2726.25,4401.25 2726.25,3981.31 2910.12,3797.45 v1(3060,3797.45) ; v1(3575,3812.45) 3715.03,3812.45 3962.54,4059.95 3962.54,4392.54 4062.46,4492.46 4278.88,4492.46 4439,4652.58 4439,4702.23 J3.6
SPI0_SLCK: J3.7 R15.1 R18.2 U2.22 | length 3943.6
  Top Layer w10: R18.2 v1@2880,4670.44 ; v1(2880,4678.15) v1@2880,4670.44 ; U2.22 3168.98,4653.98 3093.15,4578.15 2968.29,4578.15 R15.1 2880,4666.44 v1@2880,4670.44
  Bottom Layer w10: v1(2880,4678.15) 2675,4473.15 2675,3925 2865,3735 3215,3735 3277.38,3797.38 3504.5,3797.38 3531.88,3770 3775,3770 4034.96,4029.96 4034.96,4362.54 4092.46,4420.04 4265.48,4420.04 J3.7
SPI1_CSO: J3.22 R14.1 R17.2 U2.28 | length 3450.1
  Top Layer w10: R17.2 2877.5,4429.79 v1@2880,4432.29 ; v1(2880,4440) v1@2880,4432.29 ; U2.28 3035.83,4353.98 3015,4333.15 2974.14,4333.15 R14.1 2880,4427.29 v1@2880,4432.29
  Bottom Layer w10: v1(2880,4440) 2777.5,4337.5 2777.5,4147.5 3017.5,3907.5 3270,3907.5 3707.5,3907.5 3890,4090 3890,4422.59 4032.41,4565 4305,4565 4422,4682 4422,4748.16 4476.5,4802.66 J3.22
SPI1_DO: J3.5 R12.1 R23.2 U2.29 | length 3214.2
  Top Layer w10: R23.2 v1@2880,4314.72 ; v1(2880,4320) v1@2880,4314.72 ; U2.29 3400.83,4303.15 2970.43,4303.15 R12.1 2880,4310.72 v1@2880,4314.72
  Bottom Layer w10: v1(2880,4320) 2875,4320 2828.75,4273.75 2828.75,4152.42 2976.17,4005 3705,4005 3819.29,4119.29 3819.29,4451.87 4003.13,4635.71 4341.26,4635.71 4405,4699.45 4405,4776.89 J3.5
SPI1_SCLK: J3.21 R13.1 R24.2 U2.31 | length 3167.1
  Top Layer w10: R24.2 2827,4147 v1(2880,4200) 2880,4192.15 R13.1 2965.63,4106.52 3402.55,4106.52 U2.31
  Bottom Layer w10: v1(2880,4200) 2880,4150 2920,4110 3490,4110 3570,4030 3655,4030 3766.26,4141.26 3766.26,4473.84 3962.41,4670 4345,4670 4385,4710 4385,4865 4431.3,4911.3 J3.21
SW_GPB0: P11.2 U4.1 | length 532.2
  Top Layer w8: U4.1 3960,4625 4022.6,4687.6 4222.6,4687.6 4226.42,4691.42 P11.2 ; P11.2@4211.42,4762.24 4211.42,4756.03 P11.2@4215.81,4751.64
SW_GPB1: P10.2 U4.2 | length 721.2
  Top Layer w8: U4.2 3976.68,4575 4067.51,4665.83 4240.83,4665.83 4275,4700 4275,4830.68 P10.2
UART4_RXD: J3.19 P8.2 U2.11 | length 1466.3
  Top Layer w8: U2.11 3560,5043.98 3560,4900 3580,4880 P8.2 3645,4930 3693.98,4978.98 4328.25,4978.98 4479.27,5130 4583.57,5130 J3.19
UART4_TXD: J3.3 P9.2 U2.13 | length 1455
  Top Layer w8: U2.13 3525,4978.98 3525,4810 3575,4760 P9.2 3695,4810 3695,4927.9 3727.1,4960 4370.79,4960 J3.3
VOLT_SENSE: J2.8 U2.33 | length 4270.5
  Top Layer w10: J2.8 1532.55,5928.38 1959.63,5928.38 2398.38,5928.38 2520,6050 2600,6050 v1(2675,5975) ; v1(2675,5665) 2715,5625 2715,4046.42 2756.42,4005 3401.02,4005 U2.33
  Bottom Layer w10: v1(2675,5665) v1(2675,5975)
pads on no net: J1.1 J1.3 J1.4 J1.6 J1.8 J1.9 J3.36 J3.37 J3.38 J3.39 J3.40 MH1.2 MH2.2 MH3.2 MH4.2 U2.3 U2.4 U2.6 U2.7 U2.8 U2.9 U2.10 U2.14 U2.15 U2.16 U2.18 U2.30 U2.32 U2.34 U2.36 U2.38 U2.40 U2.41 U2.42 U2.103 U2.104 U2.105 U2.106 U2.111 U2.113 U2.114 U2.115 U2.116 U2.117 U2.118 U2.119 U2.120 U2.121 U2.122 U2.123 U2.124 U2.125 U2.126 U2.127 U2.128 U2.129 U2.130 U2.131 U2.132 U2.133 U2.134 U2.135 U2.136 U2.137 U2.138 U2.139 U2.140 U2.141 U2.142 U2.143 U2.144 U2.145 U2.146 U4.3 U4.4 U4.11 U4.14

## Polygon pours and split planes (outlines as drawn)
POS5V on Bottom Layer "Bottom Layer-POS5V 1" (solid, pour order 24): 1065,3998.06 1405,3658.07 1405,3439.29 1455,3389.29 1455.71,3390 1768.98,3390 2033.98,3125 4408.48,3125 4760,3476.52 4760,3935 4667.19,3935 4617.19,3985 4563.81,3985 4518.81,3940 4495,3940 3970,3415 2652.25,3415 1800,4267.25 1800,5010 1450.66,5359.34 1405,5405 1280.66,5405 1235,5359.34 1065,5359.34
POS3V3 on Bottom Layer "Bottom Layer-POS3V3" (solid, remove dead copper, pour order 34): 4760,3935 4760,4392.59 4747.59,4405 4557.63,4405 4370,4405 4230,4265 4230,4077.37 3847.63,3695 2743.5,3695 2595,3843.5 2595,5023.98 1988.98,5630 1065,5630 1065,5371.67 1223.32,5367.91 1275.41,5420 1460,5420 1860,5020 1860,4263.79 2684.5,3439.29 3955.09,3439.29 4455.76,3929.96 4460.8,3935 4506.91,3935 4506.91,3940 4551.91,3985 4617.19,3985 4667.19,3935
POS5V on Bottom Layer "Bottom Layer-POS5V" (solid, pour order 20): 3515,5515 3510,5510 3510,5315 3191.81,5315 3071.81,5435 2995,5435 2995,5460 3000,5465 3080,5465 3080,5470 3225,5615 3515,5615
GND on Top Layer "Top Layer-GND" (solid, remove dead copper, pour order 38): 4520,3100 4550,3130 4785,3130 4855,3200 4855,4666.44 4415,4666.44 4384.84,4636.28 4384.84,4377.54 4276.85,4269.55 4276.85,3686.66 4276.85,3877.43 4278.36,3878.94 4445,3878.94 4445,3854.81 4276.85,3686.66 2716.2,3686.66 2450,3952.86 2450,5164.53 2130.43,5484.1 1065,5486.5 1065,3890 1350,3890 1405,3835 1405,3170 1475,3100

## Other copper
Top Layer:
  pour cut-out: 4276.85,3686.66 4445,3854.81 4445,3878.94 4278.36,3878.94 4276.85,3877.43
  pour cut-out: 4276.85,3686.66 4445,3854.81 4445,3878.94 4278.36,3878.94 4276.85,3877.43
  text ".Layer_Name" at 1586.84,2795 h60
Bottom Layer:
  text ".Layer_Name" at 1586.84,2795 h60

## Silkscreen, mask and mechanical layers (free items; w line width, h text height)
Top Overlay:
  drawing of 10 lines, arcs and shapes, not listed
  text "CAN" at 3623.92,6175 h60 r270
  text "PWR INPUT" at 980,6140 h60
  text "LOW" at 4191.3,5732.36 h35 r90
  text "TERM" at 4191.68,5640 h35 r90
  text "TX" at 3755,5511.21 h40
  text "RX" at 3875,5510 h40
  text "HIGH" at 4191.25,5463.51 h40 r90
  text "RX" at 3900,5430 h40 r90
  text "TX" at 3900,5240 h40 r90
  text "UART4" at 3610,5050 h40
  text "I2C2" at 3880,5050 h40
  text "GPIO TEST 1" at 4095.52,5050 h40
  text "RX    GND" at 3610.83,5010 h40
  text "GND SCL" at 3880.83,5010 h40
  text "TX    GND" at 3610.83,4975 h40
  text "GND SDA" at 3880.83,4975 h40
  text "GND X 5V" at 4092.46,4975 h40
  text "*" at 3825,4666.44 h1
  text "IO CARD" at 4365,4617.44 h60 r270
  text "AUX PWR" at 1068.38,4448.28 h60 r270
  text "5V  GND" at 1145,4325 h60
  text "3V3  GND" at 1125,4145 h60
  text "Processor Breakout / REV 1 A" at 3630,3390 h60
Board Outline:
  the board outline again, w10
Mechanical 16:
  drawing of 46 lines, arcs and shapes, not listed
  text "1" at 1438.84,8477.5 h70
  text "2" at 3934.5,8477.5 h70
  text "3" at 6423.84,8477.5 h70
  text "4" at 8930.51,8477.5 h70
  text "A" at 282.5,7880 h70
  text "A" at 10925,7880 h70
  text "B" at 10922.5,6007 h70
  text "B" at 282.5,5954.5 h70
  text "C" at 10922.5,3632 h70
  text "C" at 282.5,3579.5 h70
  text "ENGINEER:" at 6397.5,1417.5 h45
  text "TITLE:" at 7897.5,1417.5 h45
  text ".Engineer" at 6437.5,1295.35 h110
  text "D" at 10922.5,1262 h70
  text "D" at 282.5,1209.5 h70
  text ".PCB_FILE_NAME_NO_PATH" at 7992.5,1169.78 h200
  text "PCB DESIGNER:" at 6397.5,1122.5 h45
  text ".Designer" at 6432.5,992.5 h110
  text "DATE:" at 6397.5,817.5 h45
  text "PART NO.:" at 7897.5,817.5 h45
  text "REV:" at 9997.5,817.5 h45
  text "Badgerloop" at 5097.5,717.5 h110
  text ".PRINT_DATE" at 6447.5,697.5 h110
  text ".Part_Number" at 7967.5,692.5 h110
  text ".Revision" at 10007.5,692.5 h110
  text "ERB Room 133" at 5097.5,617.5 h110
  text "1400 Engineering Drive" at 5097.5,517.5 h110
  text "FILE NAME:" at 6397.5,517.5 h45
  text "DWG NO:" at 7897.5,517.5 h45
  text "SCALE:" at 9997.5,517.5 h45
  text "Madison, WI 53706" at 5097.5,417.5 h110
  text ".PCB_FILE_NAME_NO_PATH" at 6447.5,397.5 h110
  text "1:1" at 10012.5,392.5 h110
  text "1" at 1438.84,177.5 h70
  text "2" at 3934.5,177.5 h70
  text "3" at 6423.84,177.5 h70
  text "4" at 8930.51,177.5 h70
Drill Drawing:
  drawing of 208 lines, arcs and shapes, not listed
  text "Symbol" at 1146.87,8134.26 h72
  text "Count" at 1428.44,8134.26 h72
  text "Hole Size" at 1720.68,8134.26 h72
  text "Plated" at 2293.15,8134.26 h72
  text "Hole Type" at 2540.35,8134.26 h72
  text "Drill Layer Pair" at 2900.24,8134.26 h72
  text "Via/Pad" at 3581.22,8134.26 h72
  text "Pad Shape" at 3876.07,8134.26 h72
  text "Template" at 4261.34,8134.26 h72
  text "55" at 1428.44,8010.3 h60
  text "28.00mil (0.711mm)" at 1720.68,8010.3 h60
  text "PTH" at 2293.15,8010.3 h60
  text "Round" at 2540.35,8010.3 h60
  text "Top Layer - Bottom Layer" at 2900.24,8010.3 h60
  text "Via" at 3581.22,8010.3 h60
  text "Rounded" at 3876.07,8010.3 h60
  text "v127h71" at 4261.34,8010.3 h60
  text "92" at 1428.44,7886.35 h60
  text "35.43mil (0.900mm)" at 1720.68,7886.35 h60
  text "PTH" at 2293.15,7886.35 h60
  text "Round" at 2540.35,7886.35 h60
  text "Top Layer - Bottom Layer" at 2900.24,7886.35 h60
  text "Pad" at 3581.22,7886.35 h60
  text "(Mixed)" at 3876.07,7886.35 h60
  text "(Mixed)" at 4261.34,7886.35 h60
  text "Layer" at 6091.33,7830 h60
  text "Name" at 6342.08,7830 h60
  text "Material" at 6826.64,7830 h60
  text "Thickness" at 7262.22,7830 h60
  text "Constant" at 7620,7830 h60
  text "Board Layer Stack" at 7951.27,7830 h60
  text "28" at 1428.44,7762.39 h60
  text "39.37mil (1.000mm)" at 1720.68,7762.39 h60
  text "PTH" at 2293.15,7762.39 h60
  text "Round" at 2540.35,7762.39 h60
  text "Top Layer - Bottom Layer" at 2900.24,7762.39 h60
  text "Pad" at 3581.22,7762.39 h60
  text "Rounded" at 3876.07,7762.39 h60
  text "c180h100" at 4261.34,7762.39 h60
  text "1" at 6091.33,7710 h60
  text "Top Overlay" at 6342.08,7710 h60
  text "24" at 1428.44,7638.43 h60
  text "42.91mil (1.090mm)" at 1720.68,7638.43 h60
  text "PTH" at 2293.15,7638.43 h60
  text "Round" at 2540.35,7638.43 h60
  text "Top Layer - Bottom Layer" at 2900.24,7638.43 h60
  text "Pad" at 3581.22,7638.43 h60
  text "(Mixed)" at 3876.07,7638.43 h60
  text "(Mixed)" at 4261.34,7638.43 h60
  text "2" at 6091.33,7590 h60
  text "Top Solder" at 6342.08,7590 h60
  text "Solder Resist" at 6826.64,7590 h60
  text "0.40mil" at 7262.22,7590 h60
  text "3.5" at 7620,7590 h60
  text "50" at 1428.44,7514.47 h60
  text "43.31mil (1.100mm)" at 1720.68,7514.47 h60
  text "PTH" at 2293.15,7514.47 h60
  text "Round" at 2540.35,7514.47 h60
  text "Top Layer - Bottom Layer" at 2900.24,7514.47 h60
  text "Pad" at 3581.22,7514.47 h60
  text "Rounded" at 3876.07,7514.47 h60
  text "c165h110" at 4261.34,7514.47 h60
  text "3" at 6091.33,7470 h60
  text "Top Layer" at 6342.08,7470 h60
  text "Copper" at 6826.64,7470 h60
  text "1.40mil" at 7262.22,7470 h60
  text "4" at 1428.44,7390.52 h60
  text "102.36mil (2.600mm)" at 1720.68,7390.52 h60
  text "NPTH" at 2293.15,7390.52 h60
  text "Round" at 2540.35,7390.52 h60
  text "Top Layer - Bottom Layer" at 2900.24,7390.52 h60
  text "Pad" at 3581.22,7390.52 h60
  text "Rounded" at 3876.07,7390.52 h60
  text "c430hn260" at 4261.34,7390.52 h60
  text "4" at 6091.33,7350 h60
  text "Dielectric 1" at 6342.08,7350 h60
  text "FR-4" at 6826.64,7350 h60
  text "12.60mil" at 7262.22,7350 h60
  text "4.8" at 7620,7350 h60
  text "2" at 1428.44,7266.56 h60
  text "122.05mil (3.100mm)" at 1720.68,7266.56 h60
  text "PTH" at 2293.15,7266.56 h60
  text "Round" at 2540.35,7266.56 h60
  text "Top Layer - Bottom Layer" at 2900.24,7266.56 h60
  text "Pad" at 3581.22,7266.56 h60
  text "Rounded" at 3876.07,7266.56 h60
  text "c351h310" at 4261.34,7266.56 h60
  text "5" at 6091.33,7230 h60
  text "Bottom Layer" at 6342.08,7230 h60
  text "Copper" at 6826.64,7230 h60
  text "1.40mil" at 7262.22,7230 h60
  text "2" at 1428.44,7142.6 h60
  text "125.20mil (3.180mm)" at 1720.68,7142.6 h60
  text "PTH" at 2293.15,7142.6 h60
  text "Round" at 2540.35,7142.6 h60
  text "Top Layer - Bottom Layer" at 2900.24,7142.6 h60
  text "Pad" at 3581.22,7142.6 h60
  text "Rounded" at 3876.07,7142.6 h60
  text "c480h318" at 4261.34,7142.6 h60
  text "6" at 6091.33,7110 h60
  text "Bottom Solder" at 6342.08,7110 h60
  text "Solder Resist" at 6826.64,7110 h60
  text "0.40mil" at 7262.22,7110 h60
  text "3.5" at 7620,7110 h60
  text "2" at 1428.44,7018.64 h60
  text "128.35mil (3.260mm)" at 1720.68,7018.64 h60
  text "PTH" at 2293.15,7018.64 h60
  text "Round" at 2540.35,7018.64 h60
  text "Top Layer - Bottom Layer" at 2900.24,7018.64 h60
  text "Pad" at 3581.22,7018.64 h60
  text "Rounded" at 3876.07,7018.64 h60
  text "c476h326" at 4261.34,7018.64 h60
  text "7" at 6091.33,6990 h60
  text "Bottom Overlay" at 6342.08,6990 h60
  text "259 Total" at 1428.44,6894.69 h60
